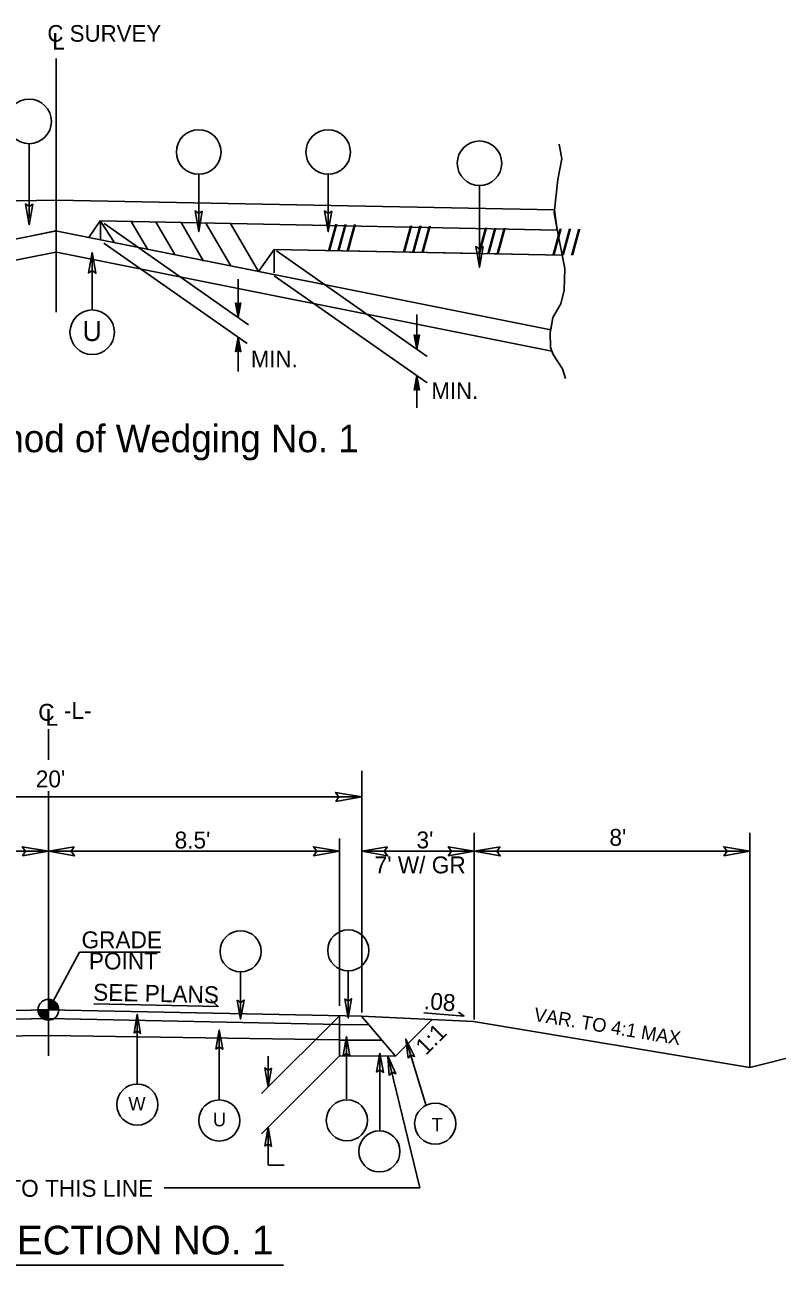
# Model space of a CAD drawing. Extents: x 106738.7 to 106779.9, y 105993.5 to 106034.9.
# Drawn here: x 106760.11 to 106766.26, y 105993.9 to 106004.05 of the extents above; entities that cross this region are included whole.
import ezdxf

# ---------------------------------------------------------------- set-up
doc = ezdxf.new("R2010")
doc.units = 0
for name, color, linetype in [('Old_Level_1', 7, 'Continuous'), ('Old_Level_11', 7, 'Continuous'), ('Old_Level_2', 7, 'Continuous'), ('Typical Detail Wedge2 CELL', 7, 'Continuous'), ('Typical Hinge Slope Arterial CELL', 7, 'Continuous'), ('Typical ID Circle CELL', 7, 'Continuous'), ('Typical Terminator CELL', 7, 'Continuous'), ('Typical Text Centerline CELL', 7, 'Continuous'), ('Typical Text General CELL', 7, 'Continuous'), ('Typical Text ID Circle CELL', 7, 'Continuous')]:
    doc.layers.add(name, color=color, linetype=linetype)

msp = doc.modelspace()

# ---------------------------------------------------------------- linework, layer by layer
at = {"layer": 'Old_Level_1'}
for p, q in [((106760.303, 105995.991), (106760.557, 105996.462)), ((106760.557, 105996.462), (106761.218, 105996.462)), ((106760.218, 105995.991), (106760.303, 105995.991)), ((106760.302, 105995.906), (106760.303, 105995.991)), ((106760.303, 105995.991), (106760.302, 105995.906)), ((106760.303, 105995.991), (106760.303, 105996.076)), ((106760.388, 105995.991), (106760.303, 105995.991)), ((106762.046, 105995.306), (106762.683, 105995.943)), ((106762.863, 105995.94), (106763.14, 105995.612)), ((106762.863, 105995.94), (106763.779, 105995.896)), ((106763.14, 105995.612), (106763.44, 105995.912)), ((106762.046, 105994.978), (106762.683, 105995.615)), ((106763.339, 105994.534), (106763.077, 105995.613)), ((106761.249, 105994.534), (106763.339, 105994.534)), ((106758.359, 105993.903), (106762.225, 105993.903))]:
    msp.add_line(p, q, dxfattribs=at)
for points in [[(106760.218, 105995.991), (106760.218, 105995.982)], [(106760.22, 105995.991), (106760.22, 105995.972)], [(106760.221, 105995.991), (106760.221, 105995.965)], [(106760.223, 105995.991), (106760.223, 105995.96)], [(106760.225, 105995.991), (106760.225, 105995.956)], [(106760.226, 105995.991), (106760.226, 105995.953)], [(106760.228, 105995.991), (106760.228, 105995.95)], [(106760.23, 105995.991), (106760.23, 105995.947)], [(106760.232, 105995.991), (106760.232, 105995.944)], [(106760.233, 105995.991), (106760.233, 105995.941)], [(106760.235, 105995.991), (106760.235, 105995.939)], [(106760.237, 105995.991), (106760.237, 105995.937)], [(106760.238, 105995.991), (106760.238, 105995.935)], [(106760.24, 105995.991), (106760.24, 105995.933)], [(106760.242, 105995.991), (106760.242, 105995.931)], [(106760.243, 105995.991), (106760.243, 105995.93)], [(106760.245, 105995.991), (106760.245, 105995.928)], [(106760.247, 105995.991), (106760.247, 105995.927)], [(106760.249, 105995.991), (106760.249, 105995.925)], [(106760.25, 105995.991), (106760.25, 105995.924)], [(106760.252, 105995.991), (106760.252, 105995.922)], [(106760.254, 105995.991), (106760.254, 105995.921)], [(106760.255, 105995.991), (106760.255, 105995.92)], [(106760.257, 105995.991), (106760.257, 105995.919)], [(106760.259, 105995.991), (106760.259, 105995.918)], [(106760.261, 105995.991), (106760.261, 105995.917)], [(106760.262, 105995.991), (106760.262, 105995.916)], [(106760.264, 105995.991), (106760.264, 105995.915)], [(106760.266, 105995.991), (106760.266, 105995.914)], [(106760.267, 105995.991), (106760.267, 105995.914)], [(106760.269, 105995.991), (106760.269, 105995.913)], [(106760.271, 105995.991), (106760.271, 105995.912)], [(106760.272, 105995.991), (106760.272, 105995.911)], [(106760.274, 105995.991), (106760.274, 105995.911)], [(106760.276, 105995.991), (106760.276, 105995.91)], [(106760.278, 105995.991), (106760.278, 105995.91)], [(106760.279, 105995.991), (106760.279, 105995.909)], [(106760.281, 105995.991), (106760.281, 105995.909)], [(106760.283, 105995.991), (106760.283, 105995.908)], [(106760.284, 105995.991), (106760.284, 105995.908)], [(106760.286, 105995.991), (106760.286, 105995.907)], [(106760.288, 105995.991), (106760.288, 105995.907)], [(106760.289, 105995.991), (106760.289, 105995.907)], [(106760.291, 105995.991), (106760.291, 105995.906)], [(106760.293, 105995.991), (106760.293, 105995.906)], [(106760.295, 105995.991), (106760.295, 105995.906)], [(106760.296, 105995.991), (106760.296, 105995.906)], [(106760.298, 105995.991), (106760.298, 105995.906)], [(106760.3, 105995.991), (106760.3, 105995.906)], [(106760.301, 105995.991), (106760.301, 105995.906), (106760.301, 105995.906)], [(106760.303, 105996.076), (106760.303, 105996.076), (106760.303, 105995.991)], [(106760.305, 105996.076), (106760.305, 105995.991)], [(106760.307, 105996.076), (106760.307, 105995.991)], [(106760.309, 105996.076), (106760.309, 105995.991)], [(106760.31, 105996.075), (106760.31, 105995.991)], [(106760.312, 105996.075), (106760.312, 105995.991)], [(106760.314, 105996.075), (106760.314, 105995.991)], [(106760.315, 105996.075), (106760.315, 105995.991)], [(106760.317, 105996.075), (106760.317, 105995.991)], [(106760.319, 105996.074), (106760.319, 105995.991)], [(106760.32, 105996.074), (106760.32, 105995.991)], [(106760.322, 105996.074), (106760.322, 105995.991)], [(106760.324, 105996.073), (106760.324, 105995.991)], [(106760.326, 105996.073), (106760.326, 105995.991)], [(106760.327, 105996.072), (106760.327, 105995.991)], [(106760.329, 105996.072), (106760.329, 105995.991)], [(106760.331, 105996.071), (106760.331, 105995.991)], [(106760.332, 105996.071), (106760.332, 105995.991)], [(106760.334, 105996.07), (106760.334, 105995.991)], [(106760.336, 105996.069), (106760.336, 105995.991)], [(106760.337, 105996.068), (106760.337, 105995.991)], [(106760.339, 105996.068), (106760.339, 105995.991)], [(106760.341, 105996.067), (106760.341, 105995.991)], [(106760.343, 105996.066), (106760.343, 105995.991)], [(106760.344, 105996.065), (106760.344, 105995.991)], [(106760.346, 105996.064), (106760.346, 105995.991)], [(106760.348, 105996.063), (106760.348, 105995.991)], [(106760.349, 105996.062), (106760.349, 105995.991)], [(106760.351, 105996.061), (106760.351, 105995.991)], [(106760.353, 105996.059), (106760.353, 105995.991)], [(106760.354, 105996.058), (106760.354, 105995.991)], [(106760.356, 105996.057), (106760.356, 105995.991)], [(106760.358, 105996.055), (106760.358, 105995.991)], [(106760.36, 105996.054), (106760.36, 105995.991)], [(106760.361, 105996.052), (106760.361, 105995.991)], [(106760.363, 105996.051), (106760.363, 105995.991)], [(106760.365, 105996.049), (106760.365, 105995.991)], [(106760.366, 105996.047), (106760.366, 105995.991)], [(106760.368, 105996.045), (106760.368, 105995.991)], [(106760.37, 105996.043), (106760.37, 105995.991)], [(106760.371, 105996.041), (106760.371, 105995.991)], [(106760.373, 105996.038), (106760.373, 105995.991)], [(106760.375, 105996.036), (106760.375, 105995.991)], [(106760.377, 105996.033), (106760.377, 105995.991)], [(106760.378, 105996.03), (106760.378, 105995.991)], [(106760.38, 105996.026), (106760.38, 105995.991)], [(106760.382, 105996.022), (106760.382, 105995.991)], [(106760.383, 105996.017), (106760.383, 105995.991)], [(106760.385, 105996.012), (106760.385, 105995.991)], [(106760.387, 105996.003), (106760.387, 105995.991)], [(106761.628, 105996.074), (106761.691, 105996.019), (106760.674, 105996.039)], [(106763.703, 105995.939), (106763.373, 105995.966)], [(106763.703, 105995.939), (106763.656, 105995.973)]]:
    msp.add_lwpolyline(points, dxfattribs=at)
msp.add_circle((106760.303, 105995.991), 0.085, dxfattribs=at)
for start, end in [(179.9905, 269.9905), (359.9905, 89.9905)]:
    msp.add_arc((106760.303, 105995.991), 0.085, start, end, dxfattribs=at)
at = {"layer": 'Old_Level_11'}
for p, q in [((106760.303, 105998.035), (106760.303, 105998.286)), ((106762.864, 105995.968), (106762.864, 105997.946)), ((106762.864, 105997.732), (106757.684, 105997.732)), ((106760.303, 105995.615), (106760.303, 105997.778)), ((106763.784, 105995.913), (106763.784, 105997.438)), ((106766.037, 105995.519), (106766.037, 105997.438)), ((106762.683, 105996.023), (106762.683, 105997.393)), ((106760.303, 105997.288), (106757.865, 105997.288)), ((106762.683, 105997.288), (106760.303, 105997.288)), ((106762.864, 105997.288), (106766.037, 105997.288)), ((106761.874, 105996.301), (106761.874, 105995.915)), ((106762.754, 105996.311), (106762.754, 105995.925)), ((106761.03, 105995.384), (106761.03, 105995.955)), ((106761.7, 105995.254), (106761.7, 105995.825)), ((106762.739, 105995.262), (106762.739, 105995.772)), ((106763.391, 105995.207), (106763.224, 105995.751)), ((106762.099, 105995.612), (106762.099, 105995.359)), ((106763.013, 105995.001), (106763.013, 105995.636)), ((106762.099, 105994.721), (106762.099, 105995.031)), ((106762.103, 105994.721), (106762.231, 105994.721))]:
    msp.add_line(p, q, dxfattribs=at)
for points in [[(106762.652, 105997.695), (106762.864, 105997.732), (106762.651, 105997.769), (106762.678, 105997.732)], [(106760.091, 105997.251), (106760.303, 105997.288), (106760.09, 105997.325), (106760.117, 105997.288)], [(106760.515, 105997.324), (106760.303, 105997.288), (106760.516, 105997.25), (106760.489, 105997.288)], [(106762.471, 105997.251), (106762.683, 105997.288), (106762.47, 105997.325), (106762.497, 105997.288)], [(106763.075, 105997.324), (106762.864, 105997.288), (106763.076, 105997.25), (106763.049, 105997.288)], [(106763.572, 105997.251), (106763.784, 105997.288), (106763.571, 105997.325), (106763.598, 105997.288)], [(106763.995, 105997.324), (106763.784, 105997.288), (106763.997, 105997.25), (106763.97, 105997.288)], [(106765.825, 105997.251), (106766.037, 105997.288), (106765.824, 105997.325), (106765.851, 105997.288)], [(106761.847, 105996.07), (106761.874, 105995.915), (106761.902, 105996.071), (106761.874, 105996.051)], [(106762.727, 105996.08), (106762.754, 105995.925), (106762.782, 105996.081), (106762.754, 105996.061)], [(106761.003, 105995.799), (106761.03, 105995.955), (106761.057, 105995.798), (106761.03, 105995.818)], [(106761.673, 105995.669), (106761.7, 105995.825), (106761.728, 105995.669), (106761.7, 105995.688)], [(106762.713, 105995.616), (106762.739, 105995.772), (106762.767, 105995.615), (106762.739, 105995.635)], [(106763.244, 105995.595), (106763.224, 105995.751), (106763.297, 105995.61), (106763.264, 105995.621)], [(106762.986, 105995.48), (106763.013, 105995.636), (106763.041, 105995.479), (106763.013, 105995.499)], [(106763.089, 105995.455), (106763.077, 105995.613), (106763.142, 105995.468), (106763.11, 105995.48)], [(106762.126, 105995.515), (106762.099, 105995.359), (106762.071, 105995.516), (106762.099, 105995.496)], [(106762.072, 105994.875), (106762.099, 105995.031), (106762.126, 105994.874), (106762.099, 105994.894)]]:
    msp.add_lwpolyline(points, close=True, dxfattribs=at)
for centre in [(106761.874, 105996.469), (106762.754, 105996.477), (106761.03, 105995.216), (106761.7, 105995.086), (106762.743, 105995.087), (106763.465, 105995.06), (106763.009, 105994.833)]:
    msp.add_circle(centre, 0.168, dxfattribs=at)
at = {"layer": 'Old_Level_2'}
for p, q in [((106760.303, 105995.991), (106757.686, 105995.938)), ((106760.303, 105995.991), (106762.863, 105995.94)), ((106757.865, 105995.872), (106760.303, 105995.921)), ((106760.303, 105995.921), (106762.683, 105995.872)), ((106762.683, 105995.615), (106762.683, 105995.943)), ((106762.683, 105995.87), (106762.923, 105995.868)), ((106757.865, 105995.745), (106760.303, 105995.782)), ((106760.303, 105995.782), (106762.683, 105995.745)), ((106762.683, 105995.742), (106763.029, 105995.743)), ((106762.683, 105995.615), (106763.14, 105995.612))]:
    msp.add_line(p, q, dxfattribs=at)
at = {"layer": 'Typical Detail Wedge2 CELL'}
for p, q in [((106760.367, 106001.696), (106760.367, 106003.771)), ((106760.367, 106001.696), (106760.367, 106003.113)), ((106760.367, 106002.613), (106756.294, 106002.532)), ((106756.294, 106002.532), (106760.367, 106002.613)), ((106760.367, 106002.613), (106764.439, 106002.532)), ((106760.367, 106002.613), (106764.439, 106002.532)), ((106764.439, 106002.532), (106764.463, 106002.368)), ((106760.727, 106002.443), (106760.633, 106002.308)), ((106760.727, 106002.443), (106760.633, 106002.308)), ((106760.721, 106002.44), (106760.727, 106002.439)), ((106760.727, 106002.443), (106764.463, 106002.368)), ((106764.463, 106002.368), (106760.727, 106002.443)), ((106760.84, 106002.268), (106760.729, 106002.441)), ((106760.729, 106002.441), (106760.729, 106002.285)), ((106760.758, 106002.421), (106761.94, 106001.593)), ((106760.981, 106002.439), (106761.114, 106002.212)), ((106761.185, 106002.429), (106761.337, 106002.168)), ((106761.388, 106002.429), (106761.572, 106002.114)), ((106761.589, 106002.425), (106761.794, 106002.074)), ((106761.792, 106002.421), (106762.02, 106002.03)), ((106760.373, 106002.362), (106756.325, 106001.553)), ((106760.361, 106002.362), (106760.101, 106002.308)), ((106760.361, 106002.362), (106764.409, 106001.553)), ((106760.633, 106002.308), (106760.361, 106002.362)), ((106760.365, 106002.188), (106756.324, 106001.38)), ((106760.368, 106002.188), (106764.419, 106001.378)), ((106760.757, 106002.26), (106761.927, 106001.44)), ((106762.148, 106002.21), (106762.02, 106002.03)), ((106762.021, 106002.03), (106762.148, 106002.21)), ((106762.148, 106002.21), (106764.502, 106002.163)), ((106762.148, 106002.21), (106762.148, 106002.019)), ((106763.827, 106002.176), (106762.148, 106002.21)), ((106762.167, 106002.197), (106763.4, 106001.333)), ((106764.502, 106002.163), (106763.827, 106002.176)), ((106762.02, 106002.03), (106762.558, 106001.923)), ((106762.148, 106001.994), (106763.398, 106001.119)), ((106761.854, 106001.966), (106761.854, 106001.654)), ((106762.558, 106001.923), (106764.409, 106001.553)), ((106761.854, 106001.654), (106761.833, 106001.773)), ((106761.854, 106001.758), (106761.833, 106001.773)), ((106761.854, 106001.654), (106761.836, 106001.771)), ((106761.854, 106001.654), (106761.875, 106001.773)), ((106761.875, 106001.773), (106761.854, 106001.758)), ((106761.872, 106001.771), (106761.854, 106001.654)), ((106761.839, 106001.769), (106761.854, 106001.654)), ((106761.854, 106001.654), (106761.842, 106001.767)), ((106761.845, 106001.764), (106761.854, 106001.654)), ((106761.854, 106001.654), (106761.848, 106001.762)), ((106761.851, 106001.76), (106761.854, 106001.654)), ((106761.854, 106001.654), (106761.869, 106001.769)), ((106761.866, 106001.767), (106761.854, 106001.654)), ((106761.854, 106001.654), (106761.863, 106001.764)), ((106761.86, 106001.762), (106761.854, 106001.654)), ((106761.854, 106001.654), (106761.857, 106001.76)), ((106761.854, 106001.758), (106761.854, 106001.654)), ((106763.315, 106001.676), (106763.315, 106001.393)), ((106761.854, 106001.492), (106761.833, 106001.372)), ((106761.836, 106001.374), (106761.854, 106001.492)), ((106761.854, 106001.492), (106761.839, 106001.376)), ((106761.842, 106001.379), (106761.854, 106001.492)), ((106761.854, 106001.492), (106761.845, 106001.381)), ((106761.848, 106001.383), (106761.854, 106001.492)), ((106761.854, 106001.492), (106761.851, 106001.385)), ((106761.854, 106001.492), (106761.854, 106001.212)), ((106761.854, 106001.492), (106761.875, 106001.372)), ((106761.854, 106001.387), (106761.854, 106001.492)), ((106761.857, 106001.385), (106761.854, 106001.492)), ((106761.854, 106001.492), (106761.86, 106001.383)), ((106761.863, 106001.381), (106761.854, 106001.492)), ((106761.854, 106001.492), (106761.866, 106001.379)), ((106761.869, 106001.376), (106761.854, 106001.492)), ((106761.854, 106001.492), (106761.872, 106001.374)), ((106763.315, 106001.393), (106763.294, 106001.512)), ((106763.315, 106001.497), (106763.294, 106001.512)), ((106763.315, 106001.393), (106763.297, 106001.51)), ((106763.3, 106001.508), (106763.315, 106001.393)), ((106763.315, 106001.393), (106763.303, 106001.506)), ((106763.306, 106001.504), (106763.315, 106001.393)), ((106763.315, 106001.393), (106763.309, 106001.501)), ((106763.312, 106001.499), (106763.315, 106001.393)), ((106763.315, 106001.393), (106763.336, 106001.512)), ((106763.336, 106001.512), (106763.315, 106001.497)), ((106763.333, 106001.51), (106763.315, 106001.393)), ((106763.315, 106001.393), (106763.33, 106001.508)), ((106763.327, 106001.506), (106763.315, 106001.393)), ((106763.315, 106001.393), (106763.324, 106001.504)), ((106763.321, 106001.501), (106763.315, 106001.393)), ((106763.315, 106001.393), (106763.318, 106001.499)), ((106763.315, 106001.497), (106763.315, 106001.393)), ((106761.833, 106001.372), (106761.854, 106001.387)), ((106761.854, 106001.387), (106761.875, 106001.372)), ((106763.315, 106001.177), (106763.294, 106001.057)), ((106763.297, 106001.059), (106763.315, 106001.177)), ((106763.315, 106001.177), (106763.3, 106001.062)), ((106763.303, 106001.064), (106763.315, 106001.177)), ((106763.315, 106001.177), (106763.306, 106001.066)), ((106763.309, 106001.068), (106763.315, 106001.177)), ((106763.315, 106001.177), (106763.312, 106001.07)), ((106763.315, 106001.177), (106763.315, 106000.914)), ((106763.315, 106001.177), (106763.336, 106001.057)), ((106763.315, 106001.073), (106763.315, 106001.177)), ((106763.318, 106001.07), (106763.315, 106001.177)), ((106763.315, 106001.177), (106763.321, 106001.068)), ((106763.324, 106001.066), (106763.315, 106001.177)), ((106763.315, 106001.177), (106763.327, 106001.064)), ((106763.33, 106001.062), (106763.315, 106001.177)), ((106763.315, 106001.177), (106763.333, 106001.059)), ((106763.294, 106001.057), (106763.315, 106001.073)), ((106763.315, 106001.073), (106763.336, 106001.057))]:
    msp.add_line(p, q, dxfattribs=at)
for points in [[(106764.477, 106003.069), (106764.499, 106002.95), (106764.466, 106002.78), (106764.437, 106002.505), (106764.477, 106002.289), (106764.524, 106002.054), (106764.52, 106001.877), (106764.491, 106001.765), (106764.426, 106001.653), (106764.405, 106001.53), (106764.408, 106001.407), (106764.43, 106001.349), (106764.506, 106001.234), (106764.531, 106001.154)], [(106764.409, 106001.553), (106764.426, 106001.653), (106764.491, 106001.765), (106764.52, 106001.877), (106764.524, 106002.054), (106764.502, 106002.163)]]:
    msp.add_lwpolyline(points, dxfattribs=at)
at = {"layer": 'Typical Hinge Slope Arterial CELL'}
for p, q in [((106766.037, 105995.519), (106763.779, 105995.896)), ((106767.165, 105995.802), (106766.037, 105995.519))]:
    msp.add_line(p, q, dxfattribs=at)
at = {"layer": 'Typical ID Circle CELL'}
for p, q in [((106760.146, 106003.075), (106760.146, 106002.464)), ((106761.532, 106002.825), (106761.532, 106002.355)), ((106762.59, 106002.825), (106762.59, 106002.355)), ((106763.827, 106002.732), (106763.827, 106002.064)), ((106760.661, 106001.714), (106760.661, 106002.184))]:
    msp.add_line(p, q, dxfattribs=at)
for centre in [(106760.146, 106003.256), (106761.532, 106003.006), (106762.59, 106003.006), (106763.827, 106002.914), (106760.661, 106001.532)]:
    msp.add_circle(centre, 0.182, dxfattribs=at)
at = {"layer": 'Typical Terminator CELL'}
for points in [[(106760.175, 106002.58), (106760.146, 106002.411), (106760.116, 106002.581), (106760.146, 106002.559)], [(106761.561, 106002.523), (106761.532, 106002.355), (106761.502, 106002.524), (106761.532, 106002.502)], [(106762.619, 106002.523), (106762.59, 106002.355), (106762.56, 106002.524), (106762.59, 106002.502)], [(106760.632, 106002.016), (106760.661, 106002.184), (106760.691, 106002.015), (106760.661, 106002.036)], [(106763.856, 106002.232), (106763.827, 106002.064), (106763.797, 106002.233), (106763.827, 106002.212)]]:
    msp.add_lwpolyline(points, close=True, dxfattribs=at)

# ---------------------------------------------------------------- texts
at = {"layer": 'Old_Level_1'}
for s, height, rotation, p in [('C', 0.138, 360, (106760.22, 105998.355)), ('L', 0.138, 360, (106760.28, 105998.314)), ('-L-', 0.1383, 360, (106760.43, 105998.37)), ('GRADE ', 0.1383, 360, (106760.574, 105996.494)), ('POINT', 0.1383, 360, (106760.634, 105996.321)), ('SEE PLANS', 0.1383, 358.7212, (106760.668, 105996.067)), ('.08', 0.1383, 355.4261, (106763.369, 105995.998)), ('1:1', 0.1383, 45, (106763.388, 105995.612)), ('W', 0.111, 360, (106760.957, 105995.168)), ('U', 0.111, 360, (106761.648, 105995.038)), ('T', 0.111, 0.14, (106763.435, 105994.996)), ('GRADE TO THIS LINE', 0.13831, 360, (106759.258, 105994.462)), ('TYPICAL SECTION NO. 1', 0.23511, 360, (106758.439, 105993.99))]:
    msp.add_text(s, height=height, rotation=rotation, dxfattribs=at).set_placement(p)
at = {"layer": 'Old_Level_11'}
for s, p in [("20'", (106760.2, 105997.81)), ("8.5'", (106761.335, 105997.31)), ("3'", (106763.312, 105997.311)), ("8'", (106764.889, 105997.332)), ("7' W/ GR ", (106762.97, 105997.107))]:
    msp.add_text(s, height=0.1383, rotation=360, dxfattribs=at).set_placement(p)
at = {"layer": 'Typical Detail Wedge2 CELL'}
for height, rotation, p in [(0.2042, 358.8553, (106762.587, 106002.203)), (0.2041, 358.8536, (106763.199, 106002.191)), (0.2042, 358.8554, (106763.811, 106002.173)), (0.2042, 358.8537, (106764.421, 106002.166))]:
    msp.add_text('/// ', height=height, rotation=rotation, dxfattribs=at).set_placement(p)
for p in [(106761.958, 106001.245), (106763.434, 106000.986)]:
    msp.add_text('MIN.', height=0.1355, dxfattribs=at).set_placement(p)
at = {"layer": 'Typical Hinge Slope Arterial CELL'}
msp.add_text('VAR. TO 4:1 MAX', height=0.1117, rotation=350.5377, dxfattribs=at).set_placement((106764.266, 105995.901))
at = {"layer": 'Typical Text Centerline CELL'}
for s, height, p in [('C SURVEY ', 0.1361, (106760.295, 106003.908)), ('L', 0.136, (106760.335, 106003.844))]:
    msp.add_text(s, height=height, dxfattribs=at).set_placement(p)
at = {"layer": 'Typical Text General CELL'}
msp.add_text('Detail Showing Method of Wedging No. 1', height=0.22457, dxfattribs=at).set_placement((106757.348, 106000.551))
at = {"layer": 'Typical Text ID Circle CELL'}
msp.add_text('U', height=0.163, dxfattribs=at).set_placement((106760.582, 106001.46))

doc.saveas('drawing.dxf')
